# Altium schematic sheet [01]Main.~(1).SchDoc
size A4; SheetNumber: 1; SheetTotal: 2
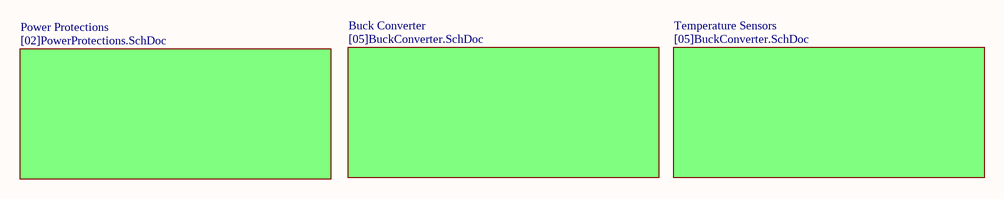
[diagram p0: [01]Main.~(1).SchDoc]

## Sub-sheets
Buck Converter = [05]BuckConverter.SchDoc: no entries
Power Protections = [02]PowerProtections.SchDoc: no entries
Temperature Sensors = [05]BuckConverter.SchDoc: no entries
